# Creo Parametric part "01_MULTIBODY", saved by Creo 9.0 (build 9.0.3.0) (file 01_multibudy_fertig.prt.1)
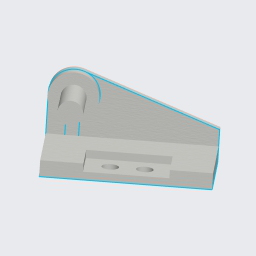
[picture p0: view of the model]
Materials in the file: S235JRG2

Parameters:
  BENENNUNG = "XXX"
  DATUM = "XX.XX.XX"
  ERSTELLER = "ARINDA"
  TEILETYP = "Fertigungsteil"
  SELECT_EN_NAME = "S235JRG2"
  SELECT_DIN_NAME = "RSt37-2"
  SELECT_DIN_NUMBER = "1.0038"
  SELECT_ASTM_NAME = "A 283 M Grade 2"
  MATERIAL_GROUP = "ME_ST_Baustahl"
  STANDARD_EN_DELIVERYSPEC = "DIN EN 10025"
  STANDARD_DIN_DELIVERYSPEC = "DIN 17100"

Other parameters: MASSE

Created from: ARINDA-STARTTEIL.PRT

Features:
  1. coordinate system "CS0"
  2. datum plane "DTM1", "T_RECHTS_Y-Z"
  3. datum plane "DTM2", "T_OBEN_X-Z"
  4. datum plane "DTM3", "T_VORNE_X-Y"
  5. datum axis "T_X-ACHSE"
  6. datum axis "A_1"
  7. datum axis "A_2"
  8. sketch "Skizze 1"
  9. sketch "Skizze 2"
  10. extrusion "Profil 1"
  11. extrusion "Profil 2"
  12. extrusion "Profil 3"
  13. extrusion "Profil 4"
  14. extrusion "Profil 5"

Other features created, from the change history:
  sketch "Skizze 2"

Other named items: T_BASIC, T_Y-ACHSE, T_Z-ACHSE

Layers: 00_STD-ACHSEN, 00_STD-EBENEN, 00_STD-KOORDSYS, 01_KURVEN, KURVENELEMENTE, VOLUMENGEOMETRIE

Surfaces: 20 plane, 13 cylinder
